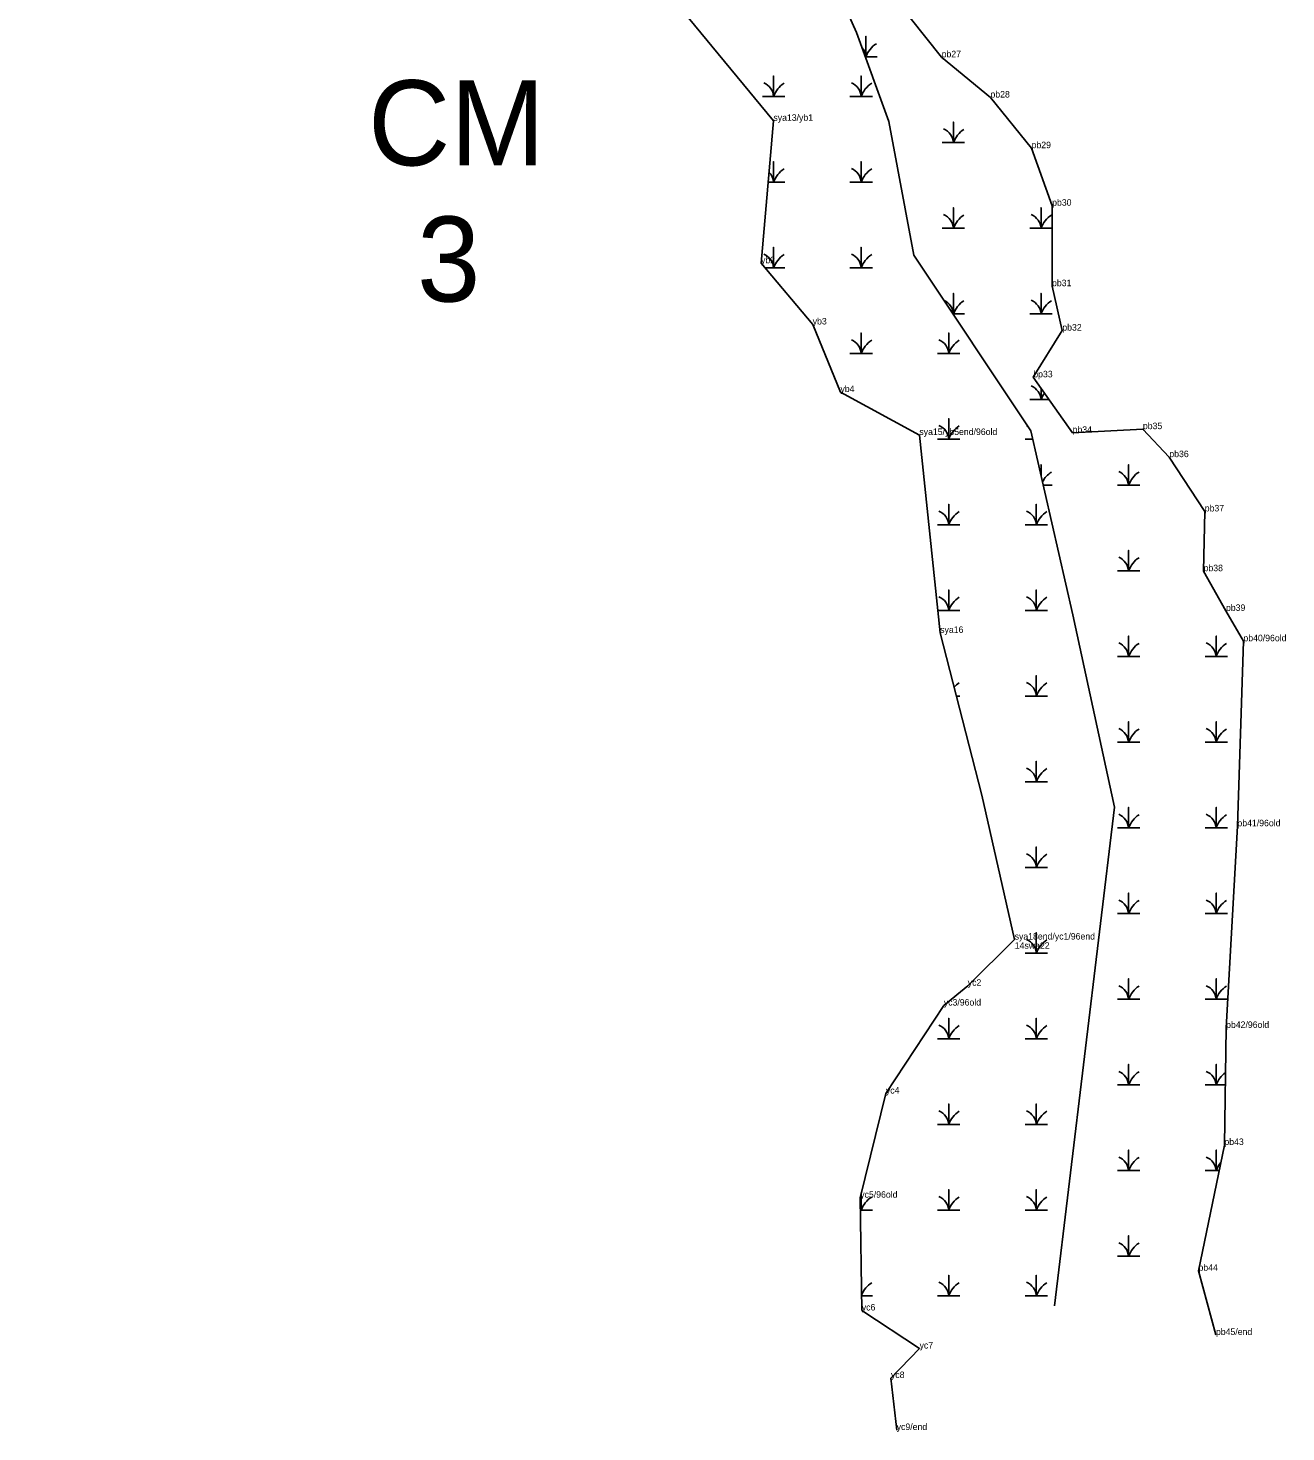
# Model space of a CAD drawing. Extents: x 2072529 to 2268796, y 436423 to 470406.
# Drawn here: x 2254541 to 2255507, y 438689 to 439767 of the extents above; entities that cross this region are included whole.
import ezdxf

# ---------------------------------------------------------------- set-up
doc = ezdxf.new("R2010")
doc.units = 0
for name, color, linetype in [('Default', 7, 'Continuous'), ('Exist Environmental Wetland Boundary Cogo Comment', 7, 'Continuous'), ('Exist Environmental Wetland Boundary Cogo Point CELL', 7, 'Continuous'), ('Old_Level_20', 7, 'Continuous'), ('Old_Level_52', 7, 'Continuous')]:
    doc.layers.add(name, color=color, linetype=linetype)

msp = doc.modelspace()

# ---------------------------------------------------------------- linework, layer by layer
at = {"layer": 'Exist Environmental Wetland Boundary Cogo Point CELL'}
for points in [[(2255183.9, 439744.6), (2255184.3, 439744.6), (2255184.3, 439760.4), (2255184.3, 439744.6), (2255192.9, 439744.6)], [(2255104.8, 439714.2), (2255113.4, 439714.2), (2255113.4, 439730), (2255113.4, 439714.2), (2255122, 439714.2)], [(2255172, 439714.2), (2255180.6, 439714.2), (2255180.6, 439730), (2255180.6, 439714.2), (2255189.2, 439714.2)], [(2255242.9, 439678.8), (2255251.5, 439678.8), (2255251.5, 439694.6), (2255251.5, 439678.8), (2255260.1, 439678.8)], [(2255109.2, 439648.4), (2255113.4, 439648.4), (2255113.4, 439664.2), (2255113.4, 439648.4), (2255122, 439648.4)], [(2255172, 439648.4), (2255180.6, 439648.4), (2255180.6, 439664.2), (2255180.6, 439648.4), (2255189.2, 439648.4)], [(2255242.9, 439613), (2255251.5, 439613), (2255251.5, 439628.8), (2255251.5, 439613), (2255260.1, 439613)], [(2255310.2, 439613), (2255318.8, 439613), (2255318.8, 439628.8), (2255318.8, 439613), (2255327.3, 439613)], [(2255106.7, 439582.6), (2255113.4, 439582.6), (2255113.4, 439598.4), (2255113.4, 439582.6), (2255122, 439582.6)], [(2255172, 439582.6), (2255180.6, 439582.6), (2255180.6, 439598.4), (2255180.6, 439582.6), (2255189.2, 439582.6)], [(2255251.2, 439547.2), (2255251.5, 439547.2), (2255251.5, 439563), (2255251.5, 439547.2), (2255260.1, 439547.2)], [(2255310.2, 439547.2), (2255318.8, 439547.2), (2255318.8, 439563), (2255318.8, 439547.2), (2255327.4, 439547.2)], [(2255172, 439516.8), (2255180.6, 439516.8), (2255180.6, 439532.6), (2255180.6, 439516.8), (2255189.2, 439516.8)], [(2255239.3, 439516.8), (2255247.9, 439516.8), (2255247.9, 439532.6), (2255247.9, 439516.8), (2255256.5, 439516.8)], [(2255310.2, 439481.4), (2255318.8, 439481.4), (2255318.8, 439490.1)], [(2255318.8, 439490.1), (2255318.8, 439481.4), (2255324.9, 439481.4)], [(2255239.3, 439451), (2255247.9, 439451), (2255247.9, 439466.8), (2255247.9, 439451), (2255256.5, 439451)], [(2255306.5, 439451), (2255312.5, 439451)], [(2255318.8, 439423.3), (2255318.8, 439431.4), (2255318.8, 439423.3)], [(2255377.4, 439415.6), (2255386, 439415.6), (2255386, 439431.4), (2255386, 439415.6), (2255394.6, 439415.6)], [(2255320.5, 439415.6), (2255327.4, 439415.6)], [(2255239.3, 439385.2), (2255247.9, 439385.2), (2255247.9, 439401), (2255247.9, 439385.2), (2255256.5, 439385.2)], [(2255306.5, 439385.2), (2255315.1, 439385.2), (2255315.1, 439401), (2255315.1, 439385.2), (2255323.7, 439385.2)], [(2255377.4, 439349.8), (2255386, 439349.8), (2255386, 439365.6), (2255386, 439349.8), (2255394.6, 439349.8)], [(2255239.5, 439319.4), (2255247.9, 439319.4), (2255247.9, 439335.2), (2255247.9, 439319.4), (2255256.5, 439319.4)], [(2255306.5, 439319.4), (2255315.1, 439319.4), (2255315.1, 439335.2), (2255315.1, 439319.4), (2255323.7, 439319.4)], [(2255377.4, 439284), (2255386, 439284), (2255386, 439299.8), (2255386, 439284), (2255394.6, 439284)], [(2255444.7, 439284), (2255453.3, 439284), (2255453.3, 439299.8), (2255453.3, 439284), (2255461.9, 439284)], [(2255306.5, 439253.6), (2255315.1, 439253.6), (2255315.1, 439269.4), (2255315.1, 439253.6), (2255323.7, 439253.6)], [(2255253.7, 439253.6), (2255256.5, 439253.6)], [(2255377.4, 439218.2), (2255386, 439218.2), (2255386, 439234), (2255386, 439218.2), (2255394.6, 439218.2)], [(2255444.7, 439218.2), (2255453.3, 439218.2), (2255453.3, 439234), (2255453.3, 439218.2), (2255461.9, 439218.2)], [(2255306.5, 439187.8), (2255315.1, 439187.8), (2255315.1, 439203.6), (2255315.1, 439187.8), (2255323.7, 439187.8)], [(2255377.4, 439152.4), (2255386, 439152.4), (2255386, 439168.2), (2255386, 439152.4), (2255394.6, 439152.4)], [(2255444.7, 439152.4), (2255453.3, 439152.4), (2255453.3, 439168.2), (2255453.3, 439152.4), (2255461.9, 439152.4)], [(2255306.5, 439122), (2255315.1, 439122), (2255315.1, 439137.8), (2255315.1, 439122), (2255323.7, 439122)], [(2255377.4, 439086.6), (2255386, 439086.6), (2255386, 439102.4), (2255386, 439086.6), (2255394.6, 439086.6)], [(2255444.7, 439086.6), (2255453.3, 439086.6), (2255453.3, 439102.4), (2255453.3, 439086.6), (2255461.9, 439086.6)], [(2255306.5, 439056.2), (2255315.1, 439056.2), (2255315.1, 439072), (2255315.1, 439056.2), (2255323.7, 439056.2)], [(2255377.4, 439020.8), (2255386, 439020.8), (2255386, 439036.6), (2255386, 439020.8), (2255394.6, 439020.8)], [(2255444.7, 439020.8), (2255453.3, 439020.8), (2255453.3, 439036.6), (2255453.3, 439020.8), (2255461.9, 439020.8)], [(2255239.3, 438990.4), (2255247.9, 438990.4), (2255247.9, 439006.2), (2255247.9, 438990.4), (2255256.5, 438990.4)], [(2255306.5, 438990.4), (2255315.1, 438990.4), (2255315.1, 439006.2), (2255315.1, 438990.4), (2255323.7, 438990.4)], [(2255377.4, 438955), (2255386, 438955), (2255386, 438970.8), (2255386, 438955), (2255394.6, 438955)], [(2255444.7, 438955), (2255453.3, 438955), (2255453.3, 438970.8), (2255453.3, 438955), (2255460.3, 438955)], [(2255239.3, 438924.6), (2255247.9, 438924.6), (2255247.9, 438940.4), (2255247.9, 438924.6), (2255256.5, 438924.6)], [(2255306.5, 438924.6), (2255315.1, 438924.6), (2255315.1, 438940.4), (2255315.1, 438924.6), (2255323.7, 438924.6)], [(2255377.4, 438889.2), (2255386, 438889.2), (2255386, 438905), (2255386, 438889.2), (2255394.6, 438889.2)], [(2255444.7, 438889.2), (2255453.3, 438889.2), (2255453.3, 438905), (2255453.3, 438889.2), (2255455.5, 438889.2)], [(2255239.3, 438858.8), (2255247.9, 438858.8), (2255247.9, 438874.6), (2255247.9, 438858.8), (2255256.5, 438858.8)], [(2255306.5, 438858.8), (2255315.1, 438858.8), (2255315.1, 438874.6), (2255315.1, 438858.8), (2255323.7, 438858.8)], [(2255180, 438858.8), (2255180.6, 438858.8), (2255180.6, 438871.4)], [(2255180.6, 438871.4), (2255180.6, 438858.8), (2255189.2, 438858.8)], [(2255377.4, 438823.4), (2255386, 438823.4), (2255386, 438839.2), (2255386, 438823.4), (2255394.6, 438823.4)], [(2255239.3, 438793), (2255247.9, 438793), (2255247.9, 438808.8), (2255247.9, 438793), (2255256.5, 438793)], [(2255306.5, 438793), (2255315.1, 438793), (2255315.1, 438808.8), (2255315.1, 438793), (2255323.7, 438793)], [(2255181, 438793), (2255189.2, 438793)]]:
    msp.add_lwpolyline(points, dxfattribs=at)
for centre, radius, start, end in [((2255172, 439743.7), 12.3, 4.1403, 41.4903), ((2255202.5, 439738.5), 19.2, 122.1274, 161.6222), ((2255101.1, 439713.3), 12.3, 4.1403, 67.535), ((2255131.6, 439708.1), 19.2, 122.1274, 161.6222), ((2255168.4, 439713.3), 12.3, 4.1403, 67.535), ((2255198.9, 439708.1), 19.2, 122.1274, 161.6222), ((2255239.2, 439677.9), 12.3, 4.1403, 67.535), ((2255269.8, 439672.7), 19.2, 122.1274, 161.6222), ((2255101.1, 439647.5), 12.3, 4.1403, 44.9085), ((2255131.6, 439642.3), 19.2, 122.1274, 161.6222), ((2255168.4, 439647.5), 12.3, 4.1403, 67.535), ((2255198.9, 439642.3), 19.2, 122.1274, 161.6222), ((2255239.2, 439612.1), 12.3, 4.1403, 67.535), ((2255269.8, 439606.9), 19.2, 122.1274, 161.6222), ((2255306.5, 439612.1), 12.3, 4.1403, 67.535), ((2255337, 439606.9), 19.2, 122.1274, 161.6222), ((2255101.1, 439581.7), 12.3, 4.1403, 67.535), ((2255131.6, 439576.5), 19.2, 122.1274, 161.6222), ((2255168.4, 439581.7), 12.3, 4.1403, 67.535), ((2255198.9, 439576.5), 19.2, 122.1274, 161.6222), ((2255239.2, 439546.3), 12.3, 4.1403, 65.473), ((2255269.8, 439541.1), 19.2, 122.1274, 161.6222), ((2255306.5, 439546.3), 12.3, 4.1403, 67.535), ((2255337, 439541.1), 19.2, 122.1274, 161.6222), ((2255168.4, 439515.9), 12.3, 4.1403, 67.535), ((2255198.9, 439510.7), 19.2, 122.1274, 161.6222), ((2255235.6, 439515.9), 12.3, 4.1403, 67.535), ((2255266.1, 439510.7), 19.2, 122.1274, 161.6222), ((2255306.5, 439480.5), 12.3, 4.1403, 67.535), ((2255337, 439475.3), 19.2, 144.6301, 161.6222), ((2255235.6, 439450.1), 12.3, 4.1403, 67.535), ((2255266.1, 439444.9), 19.2, 122.1274, 161.6222), ((2255302.9, 439450.1), 12.3, 61.8992, 67.535), ((2255337, 439409.5), 19.2, 122.1274, 152.8782), ((2255373.7, 439414.7), 12.3, 4.1403, 67.535), ((2255404.3, 439409.5), 19.2, 122.1274, 161.6222), ((2255235.6, 439384.3), 12.3, 4.1403, 67.535), ((2255266.1, 439379.1), 19.2, 122.1274, 161.6222), ((2255302.9, 439384.3), 12.3, 4.1403, 67.535), ((2255333.4, 439379.1), 19.2, 122.1274, 161.6222), ((2255373.7, 439348.9), 12.3, 4.1403, 67.535), ((2255404.3, 439343.7), 19.2, 122.1274, 161.6222), ((2255235.6, 439318.5), 12.3, 4.1403, 67.535), ((2255266.1, 439313.3), 19.2, 122.1274, 161.6222), ((2255302.9, 439318.5), 12.3, 4.1403, 67.535), ((2255333.4, 439313.3), 19.2, 122.1274, 161.6222), ((2255373.7, 439283.1), 12.3, 4.1403, 67.535), ((2255404.3, 439277.9), 19.2, 122.1274, 161.6222), ((2255441, 439283.1), 12.3, 4.1403, 67.535), ((2255471.5, 439277.9), 19.2, 122.1274, 161.6222), ((2255266.1, 439247.5), 19.2, 122.1274, 137.4546), ((2255302.9, 439252.7), 12.3, 4.1403, 67.535), ((2255333.4, 439247.5), 19.2, 122.1274, 161.6222), ((2255373.7, 439217.3), 12.3, 4.1403, 67.535), ((2255404.3, 439212.1), 19.2, 122.1274, 161.6222), ((2255441, 439217.3), 12.3, 4.1403, 67.535), ((2255471.5, 439212.1), 19.2, 122.1274, 161.6222), ((2255302.9, 439186.9), 12.3, 4.1403, 67.535), ((2255333.4, 439181.7), 19.2, 122.1274, 161.6222), ((2255373.7, 439151.5), 12.3, 4.1403, 67.535), ((2255404.3, 439146.3), 19.2, 122.1274, 161.6222), ((2255441, 439151.5), 12.3, 4.1403, 67.535), ((2255471.5, 439146.3), 19.2, 122.1274, 161.6222), ((2255302.9, 439121.1), 12.3, 4.1403, 67.535), ((2255333.4, 439115.9), 19.2, 122.1274, 161.6222), ((2255373.7, 439085.7), 12.3, 4.1403, 67.535), ((2255404.3, 439080.5), 19.2, 122.1274, 161.6222), ((2255441, 439085.7), 12.3, 4.1403, 67.535), ((2255471.5, 439080.5), 19.2, 122.1274, 161.6222), ((2255302.9, 439055.3), 12.3, 4.1403, 67.535), ((2255333.4, 439050.1), 19.2, 122.1274, 161.6222), ((2255373.7, 439019.9), 12.3, 4.1403, 67.535), ((2255404.3, 439014.7), 19.2, 122.1274, 161.6222), ((2255441, 439019.9), 12.3, 4.1403, 67.535), ((2255471.5, 439014.7), 19.2, 122.1274, 161.6222), ((2255235.6, 438989.5), 12.3, 4.1403, 67.535), ((2255266.1, 438984.3), 19.2, 122.1274, 161.6222), ((2255302.9, 438989.5), 12.3, 4.1403, 67.535), ((2255333.4, 438984.3), 19.2, 122.1274, 161.6222), ((2255373.7, 438954.1), 12.3, 4.1403, 67.535), ((2255404.3, 438948.9), 19.2, 122.1274, 161.6222), ((2255441, 438954.1), 12.3, 4.1403, 67.535), ((2255471.5, 438948.9), 19.2, 125.2068, 161.6222), ((2255235.6, 438923.7), 12.3, 4.1403, 67.535), ((2255266.1, 438918.5), 19.2, 122.1274, 161.6222), ((2255302.9, 438923.7), 12.3, 4.1403, 67.535), ((2255333.4, 438918.5), 19.2, 122.1274, 161.6222), ((2255373.7, 438888.3), 12.3, 4.1403, 67.535), ((2255404.3, 438883.1), 19.2, 122.1274, 161.6222), ((2255441, 438888.3), 12.3, 4.1403, 67.535), ((2255471.5, 438883.1), 19.2, 139.6254, 161.6222), ((2255198.9, 438852.7), 19.2, 122.1274, 161.6222), ((2255235.6, 438857.9), 12.3, 4.1403, 67.535), ((2255266.1, 438852.7), 19.2, 122.1274, 161.6222), ((2255302.9, 438857.9), 12.3, 4.1403, 67.535), ((2255333.4, 438852.7), 19.2, 122.1274, 161.6222), ((2255168.4, 438857.9), 12.3, 4.1403, 19.1048), ((2255373.7, 438822.5), 12.3, 4.1403, 67.535), ((2255404.3, 438817.3), 19.2, 122.1274, 161.6222), ((2255198.9, 438786.9), 19.2, 122.1274, 158.936), ((2255235.6, 438792.1), 12.3, 4.1403, 67.535), ((2255266.1, 438786.9), 19.2, 122.1274, 161.6222), ((2255302.9, 438792.1), 12.3, 4.1403, 67.535), ((2255333.4, 438786.9), 19.2, 122.1274, 161.6222)]:
    msp.add_arc(centre, radius, start, end, dxfattribs=at)
at = {"layer": 'Old_Level_20'}
for p, q in [((2255242.4, 439744.3), (2255242.4, 439744.3)), ((2255279.9, 439713.4), (2255279.9, 439713.4)), ((2255113.2, 439695.5), (2255113.2, 439695.5)), ((2255113.2, 439695.5), (2255113.2, 439695.5)), ((2255311.5, 439674.5), (2255311.5, 439674.5)), ((2255327.3, 439630.3), (2255327.3, 439630.3)), ((2255103.7, 439586.1), (2255103.7, 439586.1)), ((2255327.2, 439568.5), (2255327.2, 439568.5)), ((2255143.4, 439539.1), (2255143.4, 439539.1)), ((2255335.1, 439534.4), (2255335.1, 439534.4)), ((2255312.8, 439498.5), (2255312.8, 439498.5)), ((2255164.7, 439487.2), (2255164.7, 439487.2)), ((2255343, 439455.9), (2255343, 439455.9)), ((2255397, 439458.7), (2255397, 439458.7)), ((2255225.3, 439454.2), (2255225.3, 439454.2)), ((2255225.3, 439454.2), (2255225.3, 439454.2)), ((2255417.3, 439437.2), (2255417.3, 439437.2)), ((2255444.5, 439395.5), (2255444.5, 439395.5)), ((2255443.6, 439349.6), (2255443.6, 439349.6)), ((2255460.8, 439319.1), (2255460.8, 439319.1)), ((2255241.3, 439302.2), (2255241.3, 439302.2)), ((2255474.2, 439295.8), (2255474.2, 439295.8)), ((2255469.6, 439153.7), (2255469.6, 439153.7)), ((2255298.5, 439066.7), (2255298.5, 439066.7)), ((2255298.5, 439066.7), (2255298.5, 439066.7)), ((2255298.6, 439059.6), (2255298.6, 439059.6)), ((2255262.5, 439031.2), (2255262.5, 439031.2)), ((2255244.1, 439016), (2255244.1, 439016)), ((2255460.9, 438998.8), (2255460.9, 438998.8)), ((2255199.6, 438948.4), (2255199.6, 438948.4)), ((2255459.6, 438908.9), (2255459.6, 438908.9)), ((2255179.9, 438868.4), (2255179.9, 438868.4)), ((2255439.7, 438812.3), (2255439.7, 438812.3)), ((2255181.1, 438781.8), (2255181.1, 438781.8)), ((2255453.1, 438763), (2255453.1, 438763)), ((2255225.5, 438752.6), (2255225.5, 438752.6)), ((2255203.5, 438729.9), (2255203.5, 438729.9)), ((2255207.9, 438690), (2255207.9, 438690))]:
    msp.add_line(p, q, dxfattribs=at)
for points in [[(2255047.8, 439774.8), (2255113.2, 439695.5)], [(2255453.1, 438763), (2255439.7, 438812.3), (2255459.6, 438908.9), (2255460.9, 438998.8), (2255469.6, 439153.7), (2255474.2, 439295.8), (2255460.8, 439319.1), (2255443.6, 439349.6), (2255444.5, 439395.5), (2255417.3, 439437.2), (2255397, 439458.7), (2255343, 439455.9), (2255312.8, 439498.5), (2255335.1, 439534.4), (2255327.2, 439568.5), (2255327.3, 439630.3), (2255311.5, 439674.5), (2255279.9, 439713.4), (2255242.4, 439744.3), (2255218.2, 439774.6)], [(2255225.3, 439454.2), (2255164.7, 439487.2), (2255143.4, 439539.1), (2255103.7, 439586.1), (2255113.2, 439695.5)], [(2255225.3, 439454.2), (2255241.3, 439302.2), (2255273.2, 439177.7), (2255298.5, 439066.7)], [(2255298.5, 439066.7), (2255262.5, 439031.2), (2255244.1, 439016), (2255199.6, 438948.4), (2255179.9, 438868.4), (2255181.1, 438781.8), (2255225.5, 438752.6), (2255203.5, 438729.9), (2255207.9, 438690)]]:
    msp.add_lwpolyline(points, dxfattribs=at)
at = {"layer": 'Old_Level_52'}
msp.add_lwpolyline([(2254540.7, 440639.3), (2254649.9, 440510.9), (2254759, 440408.1), (2254874.5, 440228.2), (2254939.4, 440106.8), (2254987.8, 439996.7), (2255097.8, 439921.8), (2255124.2, 439851.4), (2255159.4, 439802.9), (2255177, 439763.3), (2255201.9, 439695.1), (2255221.1, 439592.3), (2255311, 439457.4), (2255343.1, 439316.1), (2255375.2, 439168.4), (2255329, 438785.5)], dxfattribs=at)

# ---------------------------------------------------------------- texts
at = {"layer": 'Default'}
for s, height, p in [('CM', 65.34, (2254801.9, 439661.3)), ('3', 65.3, (2254839.5, 439556.7))]:
    msp.add_text(s, height=height, dxfattribs=at).set_placement(p)
at = {"layer": 'Exist Environmental Wetland Boundary Cogo Comment'}
for s, p in [('pb27', (2255242.4, 439744.3)), ('pb28', (2255279.9, 439713.4)), ('sya13/yb1', (2255113.2, 439695.5)), ('sya13', (2255113.2, 439695.5)), ('pb29', (2255311.5, 439674.5)), ('pb30', (2255327.3, 439630.3)), ('yb2', (2255103.7, 439586.1)), ('pb31', (2255327.2, 439568.5)), ('yb3', (2255143.4, 439539.1)), ('pb32', (2255335.1, 439534.4)), ('bp33', (2255312.8, 439498.5)), ('yb4', (2255164.7, 439487.2)), ('sya15/yb5end/96old', (2255225.3, 439454.2)), ('pb34', (2255343, 439455.9)), ('pb35', (2255397, 439458.7)), ('pb36', (2255417.3, 439437.2)), ('pb37', (2255444.5, 439395.5)), ('pb38', (2255443.6, 439349.6)), ('pb39', (2255460.8, 439319.1)), ('sya16', (2255241.3, 439302.2)), ('pb40/96old', (2255474.2, 439295.8)), ('pb41/96old', (2255469.6, 439153.7)), ('sya18end/yc1/96end', (2255298.5, 439066.7)), ('14swa22', (2255298.6, 439059.6)), ('yc2', (2255262.5, 439031.2)), ('yc3/96old', (2255244.1, 439016)), ('pb42/96old', (2255460.9, 438998.8)), ('yc4', (2255199.6, 438948.4)), ('pb43', (2255459.6, 438908.9)), ('yc5/96old', (2255179.9, 438868.4)), ('pb44', (2255439.7, 438812.3)), ('yc6', (2255181.1, 438781.8)), ('pb45/end', (2255453.1, 438763)), ('yc7', (2255225.5, 438752.6)), ('yc8', (2255203.5, 438729.9)), ('yc9/end', (2255207.9, 438690))]:
    msp.add_text(s, height=5, dxfattribs=at).set_placement(p)

doc.saveas('drawing.dxf')
